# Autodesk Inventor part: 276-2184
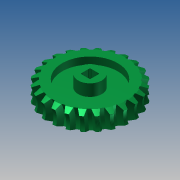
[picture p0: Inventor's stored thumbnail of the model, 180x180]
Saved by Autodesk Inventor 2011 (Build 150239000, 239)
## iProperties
Created: 2010-04
Part Number: 276-2184
Material: ABS Plastic
Document SubType Name: Modeling
Designer: Phil
Categories: <?xml version="1.0" encoding="UTF-16"?> <MemberInstance><Categories><FamilyTemplate><FamilyTemplateParameter ValueType="xs:double" Id="1" ObjectReferenceKey="da
Mass: 2.35053 g
Surface Area: 26.218 cm^2
Volume: 2.21748 cm^3
Density: 1.06 g/cm^3
Catalog Web Link: http://www.vexrobotics.com/276-2184.html
Vendor: Innovation First, Inc.
CustomPartVersion: 1
Company: Autodesk Inc.
Author: Autodesk Inc.
Title: VEX Robotics Kit of Parts
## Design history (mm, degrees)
mirror "Mirror1"
body "Solid1"
sketch "Sketch9"
  geometry: C1 r 9.398 at (0, 0); A1 r 12.447 centre (0, 0) between (-4.222, -11.709) and (-2.198, -12.251) reference
  constraints: 1 centre point, 1 coincident
  dimensions: "d94" = 18.796 diameter of C1
extrude "Extrusion1" cut sketch "Sketch9" distance "d95" = 2.3876; taper "d96" = 0 deg
sketch "Sketch10"
  geometry: C1 r 9.398 at (0, 0) reference; C2 r 4.001 at (0, 0)
  constraints: 1 centre point, 1 coincident
  dimensions: "d97" = 8.001 diameter of C2
extrude "Extrusion2" join sketch "Sketch10" distance "d98" = 3.9878; taper "d99" = 0 deg
sketch "Sketch11"
  geometry: L1 (1.612, 0.952)-(1.558, 1.007); L2 (1.558, 1.025)-(1.612, 1.079); L3 (1.612, 1.104)-(1.612, 1.079); L4 (1.558, 1.177)-(1.612, 1.231); L5 (1.612, 1.362)-(1.612, 1.231); L6 (1.232, 1.612)-(1.177, 1.558); L7 (1.159, 1.558)-(1.105, 1.612); L8 (1.079, 1.612)-(1.105, 1.612); L9 (1.232, 1.612)-(1.362, 1.612); L10 (1.612, 0.952)-(1.612, -0.952); L11 (1.558, -1.007)-(1.612, -0.952); L12 (1.612, 1.104)-(1.558, 1.159); L13 (1.079, 1.612)-(1.025, 1.558); L14 (-1.362, 1.612)-(-1.231, 1.612); L15 (-1.177, 1.558)-(-1.231, 1.612); L16 (1.007, 1.558)-(0.952, 1.612); L17 (-0.952, 1.613)-(0.952, 1.612); L18 (-0.952, 1.613)-(-1.007, 1.558); L19 (-1.024, 1.558)-(-1.079, 1.612); L20 (-1.104, 1.613)-(-1.079, 1.612); L21 (-1.104, 1.613)-(-1.159, 1.558); L22 (1.613, -1.079)-(1.558, -1.024); L23 (1.613, -1.079)-(1.612, -1.105); L24 (1.558, -1.159)-(1.612, -1.105); L25 (1.613, -1.231)-(1.558, -1.177); L26 (1.613, -1.231)-(1.612, -1.362); L27 (1.362, -1.612)-(1.231, -1.612); L28 (1.177, -1.558)-(1.231, -1.612); L29 (1.104, -1.613)-(1.079, -1.612); L30 (1.024, -1.558)-(1.079, -1.612); L31 (0.952, -1.613)-(1.007, -1.558); L32 (0.952, -1.613)-(-0.952, -1.612); L33 (1.104, -1.613)-(1.159, -1.558); L34 (-1.007, -1.558)-(-0.952, -1.612); L35 (-1.079, -1.612)-(-1.025, -1.558); L36 (-1.079, -1.612)-(-1.105, -1.612); L37 (-1.159, -1.558)-(-1.105, -1.612); L38 (-1.232, -1.612)-(-1.177, -1.558); L39 (-1.612, -0.952)-(-1.558, -1.007); L40 (-1.558, -1.025)-(-1.612, -1.079); L41 (-1.612, -1.104)-(-1.612, -1.079); L42 (-1.612, -1.104)-(-1.558, -1.159); L43 (-1.558, -1.177)-(-1.612, -1.231); L44 (-1.612, -1.362)-(-1.612, -1.231); L45 (-1.232, -1.612)-(-1.362, -1.612); L46 (-1.612, -0.952)-(-1.612, 0.952); L47 (-1.558, 1.007)-(-1.612, 0.952); L48 (-1.613, 1.079)-(-1.558, 1.024); L49 (-1.613, 1.079)-(-1.612, 1.105); L50 (-1.558, 1.159)-(-1.612, 1.105); L51 (-1.613, 1.231)-(-1.558, 1.177); L52 (-1.613, 1.231)-(-1.612, 1.362); A1 r 0.013 centre (1.567, 1.016) between (1.558, 1.025) and (1.558, 1.007); A2 r 0.013 centre (1.567, 1.168) between (1.558, 1.177) and (1.558, 1.159); A3 r 0.25 centre (1.362, 1.362) between (1.612, 1.362) and (1.362, 1.612); A4 r 0.013 centre (1.168, 1.567) between (1.159, 1.558) and (1.177, 1.558); A5 r 0.012 centre (-1.016, 1.566) between (-1.024, 1.558) and (-1.007, 1.558); A6 r 0.012 centre (-1.168, 1.566) between (-1.177, 1.558) and (-1.159, 1.558); A7 r 0.013 centre (1.016, 1.567) between (1.007, 1.558) and (1.025, 1.558); A8 r 0.012 centre (1.566, -1.016) between (1.558, -1.007) and (1.558, -1.024); A9 r 0.013 centre (1.567, -1.168) between (1.558, -1.159) and (1.558, -1.177); A10 r 0.25 centre (1.362, -1.362) between (1.362, -1.612) and (1.612, -1.362); A11 r 0.012 centre (1.168, -1.566) between (1.177, -1.558) and (1.159, -1.558); A12 r 0.012 centre (1.016, -1.566) between (1.024, -1.558) and (1.007, -1.558); A13 r 0.013 centre (-1.016, -1.567) between (-1.007, -1.558) and (-1.025, -1.558); A14 r 0.013 centre (-1.168, -1.567) between (-1.159, -1.558) and (-1.177, -1.558); A15 r 0.013 centre (-1.567, -1.168) between (-1.558, -1.177) and (-1.558, -1.159); A16 r 0.013 centre (-1.567, -1.016) between (-1.558, -1.025) and (-1.558, -1.007); A17 r 0.25 centre (-1.362, -1.362) between (-1.612, -1.362) and (-1.362, -1.612); A18 r 0.25 centre (-1.362, 1.362) between (-1.362, 1.612) and (-1.612, 1.362); A19 r 0.013 centre (-1.567, 1.168) between (-1.558, 1.159) and (-1.558, 1.177); A20 r 0.012 centre (-1.566, 1.016) between (-1.558, 1.007) and (-1.558, 1.024); 1 further point
  constraints: 104 end point, 40 point on circle, 20 centre point
feature "iFeature2:1" sketch "Sketch11"
sketch "Base Body Sketch"
  geometry: L1 (0, -14.046)-(0, 14.046) reference; L2 (0, 3.175)-(12.447, 3.175); L3 (12.447, 3.175)-(14.249, 2.308); L4 (-10.008, 0)-(60.046, 0) reference; L5 (14.249, 2.308)-(14.249, -2.308); L6 (0, -3.175)-(12.447, -3.175); L7 (0, 3.175)-(0, -3.175); L8 (12.447, -3.175)-(14.249, -2.308); C1 r 5.306 at (19.05, 0)
  constraints: 14 end point, 3 symmetric about line, 2 perpendicular, 2 point on line, 1 centre point, 1 collinear
  dimensions: "d50" = 25.6786 deg angle of L3 L2 (= da_fi); "d87" = 28.49898 diameter of L5 L1 (= da_dae); "d89" = 10.61166 diameter of C1 (= 2 x da_aw - da_da); "d92" = 6.35 distance of L2.start L6.start (= da_b); "d93" = 19.05 distance from line of C1.centre L7 (= da_aw)
revolve "Base Body2" sketch "Base Body Sketch" stored, may be unused: angle "d90" = 90 deg
workplane "Work Plane13"
sketch "Sketch8"
  geometry: C1 r 12.447 at (0, 0) reference; C2 r 12.128 at (0, 0)
  constraints: 1 centre point, 1 coincident
  dimensions: "d77" = 24.25521 diameter of C2 (= da_dw)
feature "Pitch Diameter" dims "d78" = 6.35 (= da_b), "d79" = 0
body "Srf1"
workplane "Work Plane14"
workplane "Work Plane15"
revolve "Base Body" stored, may be unused: angle "d35" = 90 deg
node "Tooth Plane"
sketch "Tooth Sketch"
  geometry: L1 (10, 5.3)-(10, -5.3) reference; L2 (-32.847, 0)-(-12.951, 0) reference; L3 (-9.05, 1.394)-(-9.05, -1.394); L4 (-9.05, -1.394)-(-3.946, -1.394); L5 (-3.946, -1.394)-(-1.521, -0.511); L6 (-1.521, -0.511)-(-1.521, 0); L7 (-1.521, 0.511)-(-3.946, 1.394); L8 (-3.946, 1.394)-(-9.05, 1.394); L9 (-1.521, 0.511)-(-1.521, 0); L10 (-2.734, 0)-(-2.734, -0.953)
  constraints: 16 end point, 4 perpendicular, 3 equal length, 2 point on line, 1 midpoint, 1 parallel, 1 vertical
  dimensions: "d38" = 19.05 distance between parallel lines of L1 L3 (= da_aw); "d39" = 20 deg angle of L7 L8 (= da_alfat); "d40" = 5.1037 distance of L7.end L3.start (= 0.5 x da_df1); "d41" = 6.31646 distance between parallel lines of L3 L10 (= 0.5 x da_d1); "d42" = 0.9525 distance of L10.start L10.end (= 0.3 x da_px)
revolve "Tooth" stored, may be unused: angle "d43" = 90 deg
pattern_circular "Tooth Pattern" dims angle "d46" = 360 deg
other parameters: "da_aw" = 19.05 [user parameter; used in 5 equation terms], "da_fi" = 25.6786 deg [user parameter; used in 1 equation term], "da_b" = 6.35 [user parameter; used in 2 equation terms], "da_df" = 23.04156 [user parameter], "da_da" = 27.48834 [user parameter; used in 1 equation term], "da_beta" = 0.7983 [user parameter; used in 1 equation term], "da_alfat" = 20 deg [user parameter; used in 1 equation term], "da_df1" = 10.2074 [user parameter; used in 1 equation term], "da_da1" = 14.65419 [user parameter], "da_d1" = 12.63292 [user parameter; used in 1 equation term], "da_px" = 3.175 [user parameter; used in 1 equation term], "d37" = -0.7983 (computed from da_rightdir, da_beta), "d68" = 19.05 (= da_aw), "d69" = 0, "d73" = 0, "d75" = 7.5 deg (computed from da_z), "da_dw" = 24.25521 [user parameter; used in 1 equation term], "da_rightdir" = 0 [user parameter; used in 1 equation term], "d80" = 0, "d81" = 0, "d82" = 0, "d83" = 7.5 deg (computed from da_z), "d84" = 0, "d85" = 180 deg, "d86" = 19.05 (= da_aw), "da_dae" = 28.49898 [user parameter; used in 1 equation term]
